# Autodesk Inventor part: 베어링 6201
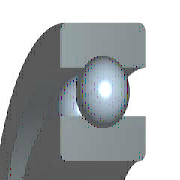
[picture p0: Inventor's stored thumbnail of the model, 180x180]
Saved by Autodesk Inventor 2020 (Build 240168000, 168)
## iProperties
Created: 2012-02
Part Number: 베어링 6201
Material: 강철, 연강
Description: 깊은 그루브 볼 베어링
Document SubType Name: Modeling
Standard: KS B 2023
Designer: test
Standards Organization: KS
Language: ko-KR
Size Designation: 6201 - 12 x 32 x 10
Categories: <MemberInstance><Categories><Category DisplayName="샤프트 부품" InternalName="7f7aeb1f-a693-4053-b835-cee3144e0d98" Mnemonic="SHFT"><Category DisplayName="베어링" Inter
Density: 1 g/cm^3
Appearance: 노란색
IsCustomPart: 1
Author: test
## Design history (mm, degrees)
sketch "스케치" dims "d0" = 5.2 (= -0.26 x WD + 0.26 x BD)
  geometry: L1 (2.4, 11)-(7.6, 11); L2 (5, 11)-(5, 8.4); L3 (5, 11)-(5, 13.6); L4 (3.068, 9.26)-(0, 9.26); L5 (0, 6)-(10, 6); L6 (3.068, 12.74)-(0, 12.74); L7 (0, 16)-(10, 16); L8 (10, 6)-(10, 9.26); L9 (6.932, 9.26)-(10, 9.26); L10 (6.932, 12.74)-(10, 12.74); L11 (10, 16)-(10, 12.74); L12 (-1.4, 0)-(8.4, 0) reference; L13 (0, -0.3)-(0, 5.3) reference
  constraints: 22 end point, 4 point on line, 2 collinear, 2 perpendicular, 2 symmetric about line, 1 midpoint, 1 parallel, 14 other
  dimensions: "d9" = 12 diameter of L5 L12 (= WD); "d11" = 32 diameter of L7 L12 (= BD); "d12" = 10 distance between parallel lines of L8 L13 (= KB); "d13" = 18.52 diameter of L9 L12 (= 0.326 x BD + 0.674 x WD)
revolve "본체" stored, may be unused: angle "d6" = 90 deg
revolve "볼" stored, may be unused: angle "d7" = 90 deg
pattern_circular "IDS_ARRAYBALL[SIMPL:T]" dims angle "d3" = 360 deg
body "Solid1"
fillet "모깎기1" dims "d1" = 0.6 (= KRS)
other parameters: "WD" = 12 [user parameter; used in 5 equation terms], "BD" = 32 [user parameter; used in 5 equation terms], "KB" = 10 [user parameter; used in 1 equation term], "KRS" = 0.6 [user parameter; used in 1 equation term], "d4" = 0, "d5" = 0, "d8" = 0, "d14" = 0, "d15" = 0, "BBA" = 0 [user parameter], "BC0" = 3100000 [user parameter], "BC" = 6890000 [user parameter], "BR" = 16 (= 0.5 x BD) [user parameter], "WR" = 6 (= 0.5 x WD) [user parameter]
